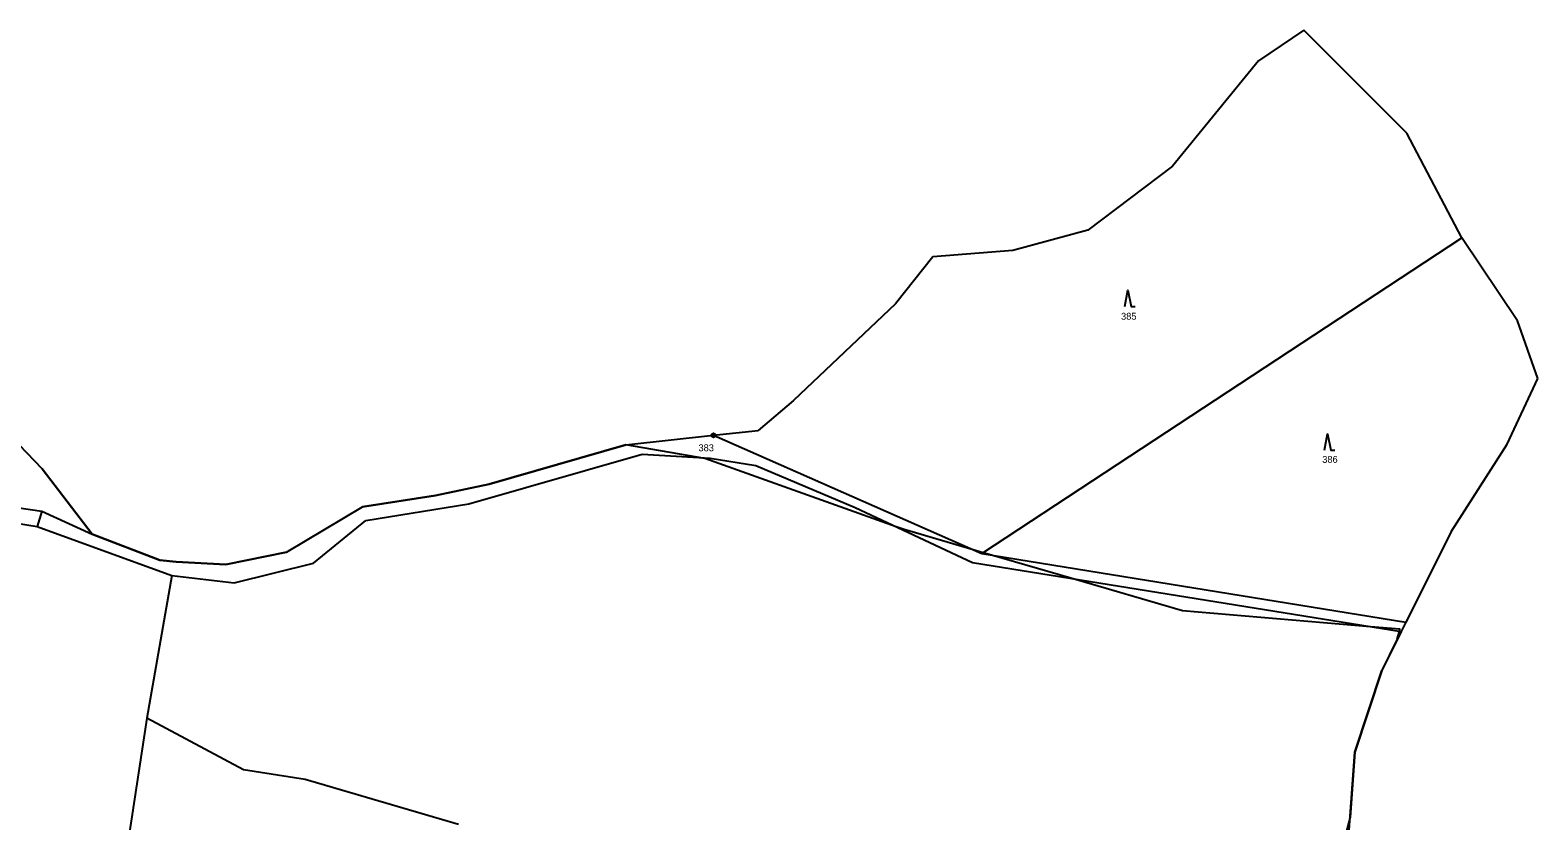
# Model space of a CAD drawing. Extents: x -547623 to -538651, y -1096714 to -1086522.
# Drawn here: x -541230.9 to -540860.1, y -1091618.7 to -1091424.1 of the extents above; entities that cross this region are included whole.
import ezdxf

# ---------------------------------------------------------------- set-up
doc = ezdxf.new("R2010")
doc.units = 0
for name, color, linetype in [('Vrstva 1', 7, 'Continuous'), ('Vrstva 25', 7, 'Continuous'), ('Vrstva 41', 7, 'Continuous'), ('Vrstva 52', 7, 'Continuous'), ('Vrstva 83', 7, 'Continuous'), ('Vrstva 86', 7, 'Continuous')]:
    doc.layers.add(name, color=color, linetype=linetype)

msp = doc.modelspace()

# ---------------------------------------------------------------- linework, layer by layer
at = {"layer": 'Vrstva 1'}
for points in [[(-540996.88, -1091552.89), (-540878.79, -1091475.2)], [(-541062.86, -1091523.8), (-540996.88, -1091552.89)], [(-541123.05, -1091540.62), (-541080.37, -1091528.46)], [(-541080.37, -1091528.46), (-541063.64, -1091529.38)], [(-541063.64, -1091529.38), (-541052.45, -1091531.19)], [(-541052.45, -1091531.19), (-541028.04, -1091541.59)], [(-541267.95, -1091536.66), (-541228.05, -1091542.44)], [(-541267.81, -1091540), (-541229.25, -1091546.21)], [(-541148.41, -1091544.79), (-541123.05, -1091540.62)], [(-541228.05, -1091542.44), (-541229.25, -1091546.21)], [(-541228.05, -1091542.44), (-541215.73, -1091548.16)], [(-541161.21, -1091555.3), (-541148.41, -1091544.79)], [(-541028.04, -1091541.59), (-540999.19, -1091555.06)], [(-541229.25, -1091546.21), (-541196.12, -1091558.29)], [(-541180.77, -1091560.09), (-541161.21, -1091555.3)], [(-540999.19, -1091555.06), (-540893.72, -1091572.11)], [(-540996.88, -1091552.89), (-540892.57, -1091569.82)], [(-541196.12, -1091558.29), (-541202.22, -1091593.38)], [(-541196.12, -1091558.29), (-541180.77, -1091560.09)], [(-541202.22, -1091593.38), (-541223.54, -1091733.4)], [(-541178.5, -1091606.11), (-541202.22, -1091593.38)], [(-541163.3, -1091608.46), (-541178.5, -1091606.11)], [(-541125.62, -1091619.59), (-541163.3, -1091608.46)]]:
    msp.add_lwpolyline(points, dxfattribs=at)
at = {"layer": 'Vrstva 25'}
for points in [[(-540961.66, -1091492.07), (-540960.96, -1091488.07), (-540960.16, -1091492.07), (-540959.16, -1091492.07)], [(-540912.54, -1091527.42), (-540911.84, -1091523.42), (-540911.04, -1091527.42), (-540910.04, -1091527.42)]]:
    msp.add_lwpolyline(points, dxfattribs=at)
at = {"layer": 'Vrstva 41'}
for points in [[(-540917.62, -1091424.08), (-540928.84, -1091431.67)], [(-540892.32, -1091449.46), (-540917.62, -1091424.08)], [(-540928.84, -1091431.67), (-540949.99, -1091457.53)], [(-540878.79, -1091475.2), (-540892.32, -1091449.46)], [(-540949.99, -1091457.53), (-540970.76, -1091473.31)], [(-540970.76, -1091473.31), (-540989.25, -1091478.28)], [(-540865.06, -1091495.66), (-540878.79, -1091475.2)], [(-541008.94, -1091479.86), (-541018.06, -1091491.46)], [(-540989.25, -1091478.28), (-541008.94, -1091479.86)], [(-541018.06, -1091491.46), (-541043.18, -1091515.21)], [(-540860.09, -1091509.83), (-540865.06, -1091495.66)], [(-541228.01, -1091532.06), (-541248.82, -1091510.36)], [(-540867.61, -1091525.99), (-540860.09, -1091509.83)], [(-541043.18, -1091515.21), (-541051.84, -1091522.6)], [(-541062.86, -1091523.8), (-541051.84, -1091522.6)], [(-541084.42, -1091526.16), (-541118.07, -1091535.82)], [(-541084.42, -1091526.16), (-541062.86, -1091523.8)], [(-540881.31, -1091547.35), (-540867.61, -1091525.99)], [(-541215.73, -1091548.16), (-541228.01, -1091532.06)], [(-541118.07, -1091535.82), (-541131.21, -1091538.64)], [(-541131.21, -1091538.64), (-541149.21, -1091541.41)], [(-541167.9, -1091552.52), (-541149.21, -1091541.41)], [(-541199.08, -1091554.53), (-541215.73, -1091548.16)], [(-540881.31, -1091547.35), (-540892.57, -1091569.82)], [(-541195, -1091554.92), (-541199.08, -1091554.53)], [(-541182.85, -1091555.6), (-541195, -1091554.92)], [(-541167.9, -1091552.52), (-541182.85, -1091555.6)], [(-540892.57, -1091569.82), (-540893.72, -1091572.11)], [(-540893.72, -1091572.11), (-540898.5, -1091581.65)], [(-540905.13, -1091601.74), (-540898.5, -1091581.65)], [(-540906.58, -1091622.02), (-540905.13, -1091601.74)]]:
    msp.add_lwpolyline(points, dxfattribs=at)
at = {"layer": 'Vrstva 52'}
for points in [[(-541248.82, -1091510.36), (-541228.01, -1091532.06), (-541215.73, -1091548.16), (-541199.08, -1091554.53), (-541195, -1091554.92), (-541182.85, -1091555.6), (-541167.9, -1091552.52), (-541149.21, -1091541.41), (-541131.21, -1091538.64), (-541118.07, -1091535.82), (-541084.42, -1091526.16)], [(-541065, -1091529.5), (-541084.42, -1091526.16)], [(-540894.66, -1091573.99), (-540894.14, -1091572.04), (-540894, -1091571.5), (-540901.28, -1091570.89), (-540947.5, -1091567), (-540975, -1091558.97), (-540994.51, -1091553.27), (-540996.56, -1091552.68), (-540998.95, -1091551.98), (-541016, -1091547), (-541017.93, -1091546.31), (-541065, -1091529.5)], [(-540894.66, -1091573.99), (-540898.5, -1091581.65), (-540905.13, -1091601.74), (-540906.28, -1091617.77)], [(-540906.28, -1091617.77), (-540913.5, -1091645), (-540912.5, -1091690.5), (-540912.33, -1091703.96)]]:
    msp.add_lwpolyline(points, dxfattribs=at)
at = {"layer": 'Vrstva 83'}
for radius in [0.5, 0.1]:
    msp.add_circle((-541062.86, -1091523.8), radius, dxfattribs=at)

# ---------------------------------------------------------------- texts
at = {"layer": 'Vrstva 86'}
for s, p in [('385', (-540962.61, -1091495.35)), ('383', (-541066.55, -1091527.72)), ('386', (-540913.12, -1091530.57))]:
    msp.add_text(s, height=1.7, dxfattribs=at).set_placement(p)

doc.saveas('drawing.dxf')
